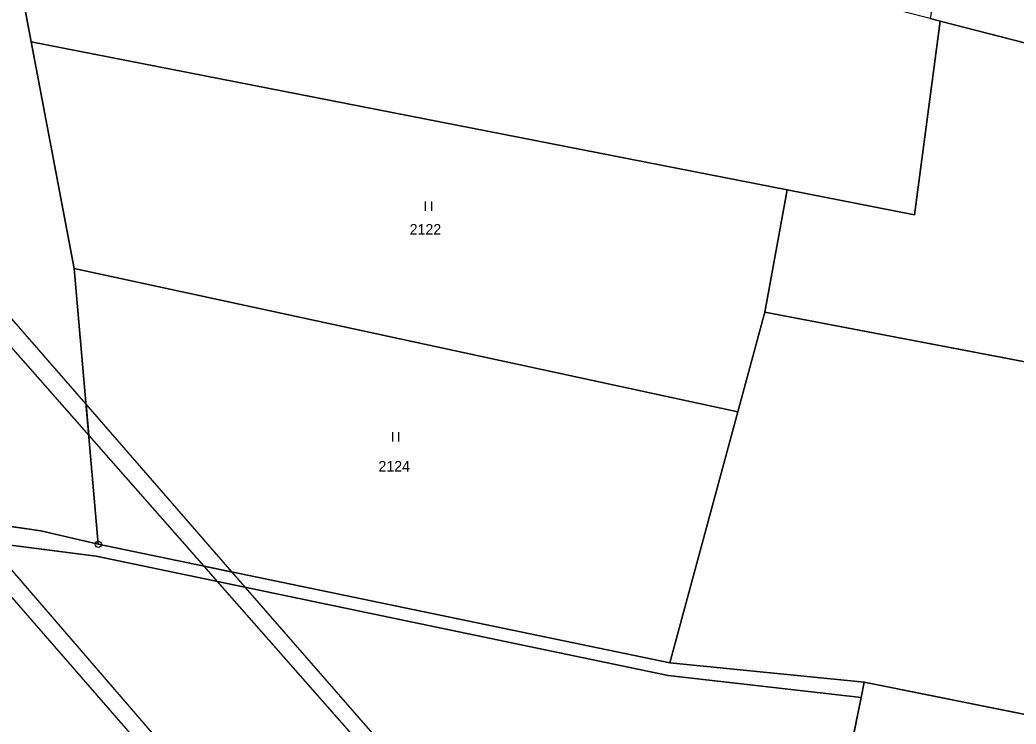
# Model space of a CAD drawing. Extents: x -689422 to -685210, y -987725 to -982160.
# Drawn here: x -686974.8 to -686815, y -986529.1 to -986416.1 of the extents above; entities that cross this region are included whole.
import ezdxf

# ---------------------------------------------------------------- set-up
doc = ezdxf.new("R2010")
doc.units = 0
for name, color, linetype in [('KN_Hranice_parcel', 7, 'Continuous'), ('KN_Parcelni cisla', 7, 'Continuous'), ('KN_Polygon parcely', 7, 'Continuous'), ('KN_POZEMKY_ORNA PUDA', 7, 'Continuous'), ('KN_POZEMKY_OSTATNI PLOCHA', 7, 'Continuous'), ('KN_POZEMKY_TTP', 7, 'Continuous'), ('KN_VYUZITI_17_ostatni plocha_ostatni komunikace', 7, 'Continuous'), ('KN_Věcná břemena k části', 7, 'Continuous'), ('KN_Značky bodu BP', 7, 'Continuous'), ('KN_Značky kultur', 7, 'Continuous')]:
    doc.layers.add(name, color=color, linetype=linetype)

msp = doc.modelspace()

# ---------------------------------------------------------------- linework, layer by layer
at = {"layer": 'KN_Hranice_parcel'}
for p, q in [((-686972.93, -986419.65), (-686976.58, -986400.39)), ((-686827.2, -986416.35), (-686828.79, -986415.94)), ((-686827.2, -986416.35), (-686761.86, -986433.13)), ((-686851.7, -986443.4), (-686972.93, -986419.65)), ((-686966.05, -986456.01), (-686972.93, -986419.65)), ((-686855.29, -986463.03), (-686851.7, -986443.4)), ((-686966.05, -986456.01), (-686859.62, -986479.02)), ((-686962.2, -986500.29), (-686966.05, -986456.01)), ((-686859.62, -986479.02), (-686855.29, -986463.03)), ((-686747.75, -986483.59), (-686855.29, -986463.03)), ((-686870.56, -986519.29), (-686859.62, -986479.02)), ((-686870.56, -986519.29), (-686962.2, -986500.29)), ((-686839.35, -986522.39), (-686870.56, -986519.29)), ((-686839.83, -986524.86), (-686839.35, -986522.39)), ((-686839.35, -986522.39), (-686805.32, -986529.23)), ((-686859.86, -986622.32), (-686839.83, -986524.86))]:
    msp.add_line(p, q, dxfattribs=at)
for points in [[(-686851.7, -986443.4), (-686831.28, -986447.4), (-686827.2, -986416.35)], [(-687072.52, -986489.67), (-687024.37, -986494.67), (-686994.67, -986494.79), (-686971.4, -986498.12), (-686962.2, -986500.29)], [(-686989.98, -986498.65), (-686962.52, -986502.21), (-686870.81, -986521.35), (-686839.83, -986524.86)]]:
    msp.add_lwpolyline(points, dxfattribs=at)
at = {"layer": 'KN_Polygon parcely'}
for points in [[(-686976.58, -986400.39), (-686982.93, -986401.96), (-686979.74, -986376.53), (-686987.67, -986344.74), (-687048.6, -986343.58), (-687096.49, -986346.04), (-687085.65, -986397.07), (-687078.04, -986479.92), (-687072.52, -986489.67), (-687024.37, -986494.67), (-686994.67, -986494.79), (-686971.4, -986498.12), (-686962.2, -986500.29), (-686966.05, -986456.01), (-686972.93, -986419.65)], [(-686764.24, -986372.62), (-686767.99, -986368.53), (-686817.53, -986351.74), (-686828.79, -986415.94), (-686827.2, -986416.35), (-686761.86, -986433.13), (-686755.12, -986414.77), (-686753.86, -986393.15)], [(-686828.79, -986415.94), (-686845.68, -986411.61), (-686843.89, -986398.98), (-686838.96, -986382.8), (-686869.76, -986369.49), (-686876.69, -986398.36), (-686908.5, -986385.84), (-686941.74, -986376.72), (-686979.74, -986376.53), (-686982.93, -986401.96), (-686976.58, -986400.39), (-686972.93, -986419.65), (-686851.7, -986443.4), (-686831.28, -986447.4), (-686827.2, -986416.35)], [(-686720.14, -986445.5), (-686741.89, -986439.01), (-686760.1, -986433.58), (-686761.86, -986433.13), (-686827.2, -986416.35), (-686831.28, -986447.4), (-686851.7, -986443.4), (-686855.29, -986463.03), (-686747.75, -986483.59)], [(-686859.62, -986479.02), (-686855.29, -986463.03), (-686851.7, -986443.4), (-686972.93, -986419.65), (-686966.05, -986456.01)], [(-686870.56, -986519.29), (-686859.62, -986479.02), (-686966.05, -986456.01), (-686962.2, -986500.29)], [(-686753.43, -986505.25), (-686747.75, -986483.59), (-686855.29, -986463.03), (-686859.62, -986479.02), (-686870.56, -986519.29), (-686839.35, -986522.39), (-686805.32, -986529.23), (-686767.44, -986536.84), (-686764.84, -986537.36), (-686760.96, -986516.48)], [(-686989.98, -986498.65), (-686962.52, -986502.21), (-686870.81, -986521.35), (-686839.83, -986524.86), (-686839.35, -986522.39), (-686870.56, -986519.29), (-686962.2, -986500.29), (-686971.4, -986498.12), (-686994.67, -986494.79), (-687024.37, -986494.67), (-687072.52, -986489.67), (-687080.7, -986488.8), (-687080.36, -986492.73), (-687075.26, -986493.53), (-687066.49, -986494.06), (-687013.58, -986497.26)], [(-686859.86, -986622.32), (-686839.83, -986524.86), (-686870.81, -986521.35), (-686962.52, -986502.21), (-686989.98, -986498.65), (-687013.58, -986497.26), (-687066.49, -986494.06), (-687063.42, -986524.56), (-687063.23, -986605.59), (-687019.91, -986606.34), (-687000.29, -986608.91), (-686950.94, -986614.98), (-686915.66, -986618.74)], [(-686805.32, -986529.23), (-686839.35, -986522.39), (-686839.83, -986524.86), (-686859.86, -986622.32), (-686834.62, -986626.15)]]:
    msp.add_lwpolyline(points, close=True, dxfattribs=at)
at = {"layer": 'KN_POZEMKY_ORNA PUDA'}
for p, q in [((-686989.98, -986498.65), (-686962.52, -986502.21)), ((-686962.52, -986502.21), (-686870.81, -986521.35)), ((-686870.81, -986521.35), (-686839.83, -986524.86)), ((-686839.83, -986524.86), (-686859.86, -986622.32))]:
    msp.add_line(p, q, dxfattribs=at)
at = {"layer": 'KN_POZEMKY_OSTATNI PLOCHA'}
for p, q in [((-686994.67, -986494.79), (-686971.4, -986498.12)), ((-686971.4, -986498.12), (-686962.2, -986500.29)), ((-686962.52, -986502.21), (-686989.98, -986498.65)), ((-686962.2, -986500.29), (-686870.56, -986519.29)), ((-686870.81, -986521.35), (-686962.52, -986502.21)), ((-686870.56, -986519.29), (-686839.35, -986522.39)), ((-686839.83, -986524.86), (-686870.81, -986521.35)), ((-686839.35, -986522.39), (-686839.83, -986524.86))]:
    msp.add_line(p, q, dxfattribs=at)
at = {"layer": 'KN_POZEMKY_TTP'}
for p, q in [((-686976.58, -986400.39), (-686972.93, -986419.65)), ((-686972.93, -986419.65), (-686976.58, -986400.39)), ((-686827.2, -986416.35), (-686831.28, -986447.4)), ((-686831.28, -986447.4), (-686827.2, -986416.35)), ((-686827.2, -986416.35), (-686828.79, -986415.94)), ((-686828.79, -986415.94), (-686827.2, -986416.35)), ((-686761.86, -986433.13), (-686827.2, -986416.35)), ((-686827.2, -986416.35), (-686761.86, -986433.13)), ((-686972.93, -986419.65), (-686966.05, -986456.01)), ((-686966.05, -986456.01), (-686972.93, -986419.65)), ((-686972.93, -986419.65), (-686851.7, -986443.4)), ((-686851.7, -986443.4), (-686972.93, -986419.65)), ((-686851.7, -986443.4), (-686855.29, -986463.03)), ((-686855.29, -986463.03), (-686851.7, -986443.4)), ((-686831.28, -986447.4), (-686851.7, -986443.4)), ((-686851.7, -986443.4), (-686831.28, -986447.4)), ((-686966.05, -986456.01), (-686962.2, -986500.29)), ((-686962.2, -986500.29), (-686966.05, -986456.01)), ((-686966.05, -986456.01), (-686859.62, -986479.02)), ((-686859.62, -986479.02), (-686966.05, -986456.01)), ((-686855.29, -986463.03), (-686859.62, -986479.02)), ((-686859.62, -986479.02), (-686855.29, -986463.03)), ((-686855.29, -986463.03), (-686747.75, -986483.59)), ((-686747.75, -986483.59), (-686855.29, -986463.03)), ((-686859.62, -986479.02), (-686870.56, -986519.29)), ((-686870.56, -986519.29), (-686859.62, -986479.02)), ((-686971.4, -986498.12), (-686994.67, -986494.79)), ((-686962.2, -986500.29), (-686971.4, -986498.12)), ((-686870.56, -986519.29), (-686962.2, -986500.29)), ((-686839.35, -986522.39), (-686870.56, -986519.29)), ((-686839.83, -986524.86), (-686839.35, -986522.39)), ((-686839.35, -986522.39), (-686805.32, -986529.23)), ((-686805.32, -986529.23), (-686839.35, -986522.39)), ((-686859.86, -986622.32), (-686839.83, -986524.86))]:
    msp.add_line(p, q, dxfattribs=at)
at = {"layer": 'KN_VYUZITI_17_ostatni plocha_ostatni komunikace'}
for p, q in [((-686994.67, -986494.79), (-686971.4, -986498.12)), ((-686971.4, -986498.12), (-686962.2, -986500.29)), ((-686962.52, -986502.21), (-686989.98, -986498.65)), ((-686962.2, -986500.29), (-686870.56, -986519.29)), ((-686870.81, -986521.35), (-686962.52, -986502.21)), ((-686870.56, -986519.29), (-686839.35, -986522.39)), ((-686839.83, -986524.86), (-686870.81, -986521.35)), ((-686839.35, -986522.39), (-686839.83, -986524.86))]:
    msp.add_line(p, q, dxfattribs=at)
at = {"layer": 'KN_Věcná břemena k části'}
for points in [[(-686963.72, -986482.82), (-686964.15, -986477.81), (-687034, -986397.57), (-687079.62, -986345.17), (-687084, -986345.4), (-687036.6, -986399.91)], [(-686964.15, -986477.81), (-686963.72, -986482.82), (-686945.28, -986503.8), (-686940.71, -986504.75)], [(-686878.31, -986621.14), (-686874.77, -986621.36), (-686918.41, -986571.32), (-686979.93, -986499.95), (-686982.93, -986496.47), (-686987.45, -986495.82), (-686984.36, -986499.38), (-686920.3, -986572.96)], [(-686838.78, -986625.52), (-686835.03, -986626.09), (-686855.75, -986602.31), (-686898.13, -986553.66), (-686938.56, -986507.21), (-686940.71, -986504.75), (-686945.28, -986503.8), (-686943.12, -986506.26), (-686900.01, -986555.3), (-686856.37, -986605.34)]]:
    msp.add_lwpolyline(points, close=True, dxfattribs=at)
at = {"layer": 'KN_Značky bodu BP'}
for radius in [0.5, 0.0303]:
    msp.add_circle((-686962.2, -986500.29), radius, dxfattribs=at)
at = {"layer": 'KN_Značky kultur'}
for p, q in [((-686909.72, -986446.77), (-686909.72, -986445.27)), ((-686908.72, -986446.77), (-686908.72, -986445.27)), ((-686914.97, -986483.79), (-686914.97, -986482.29)), ((-686913.97, -986483.79), (-686913.97, -986482.29))]:
    msp.add_line(p, q, dxfattribs=at)

# ---------------------------------------------------------------- texts
at = {"layer": 'KN_Parcelni cisla'}
for s, p in [('2122', (-686912.26, -986450.6)), ('2124', (-686917.26, -986488.62))]:
    msp.add_text(s, height=1.7, dxfattribs=at).set_placement(p)

doc.saveas('drawing.dxf')
